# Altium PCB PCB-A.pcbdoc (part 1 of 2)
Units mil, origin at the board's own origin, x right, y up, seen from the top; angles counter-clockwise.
Board outline 6045 x 2702.2 mil, 4 copper layers (Top Layer, Inner1, Inner2, Bottom Layer); 82 components, 118 nets, 419 pads, 214 vias.
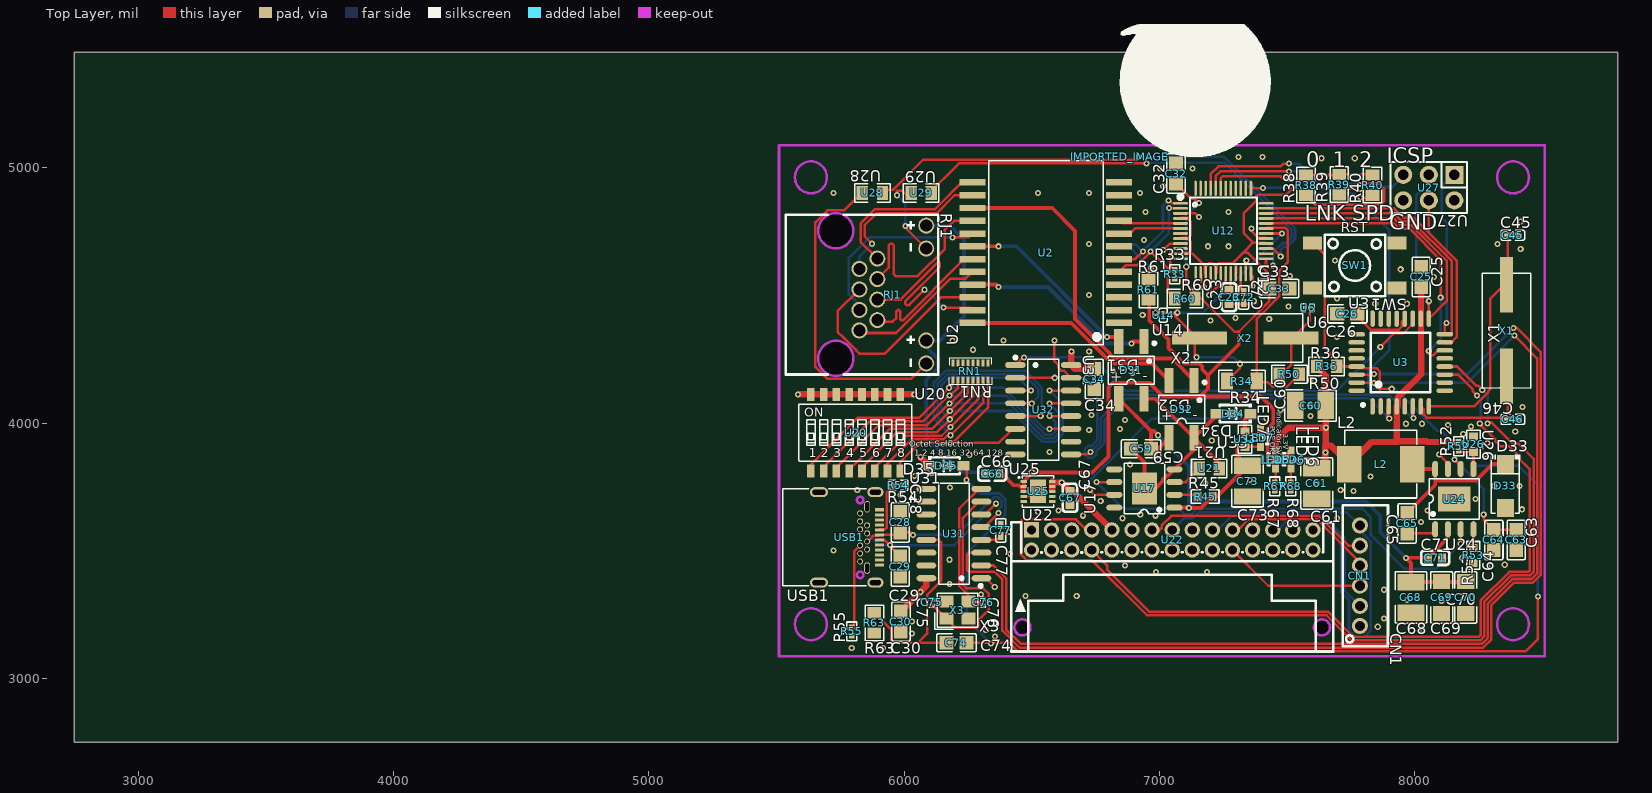
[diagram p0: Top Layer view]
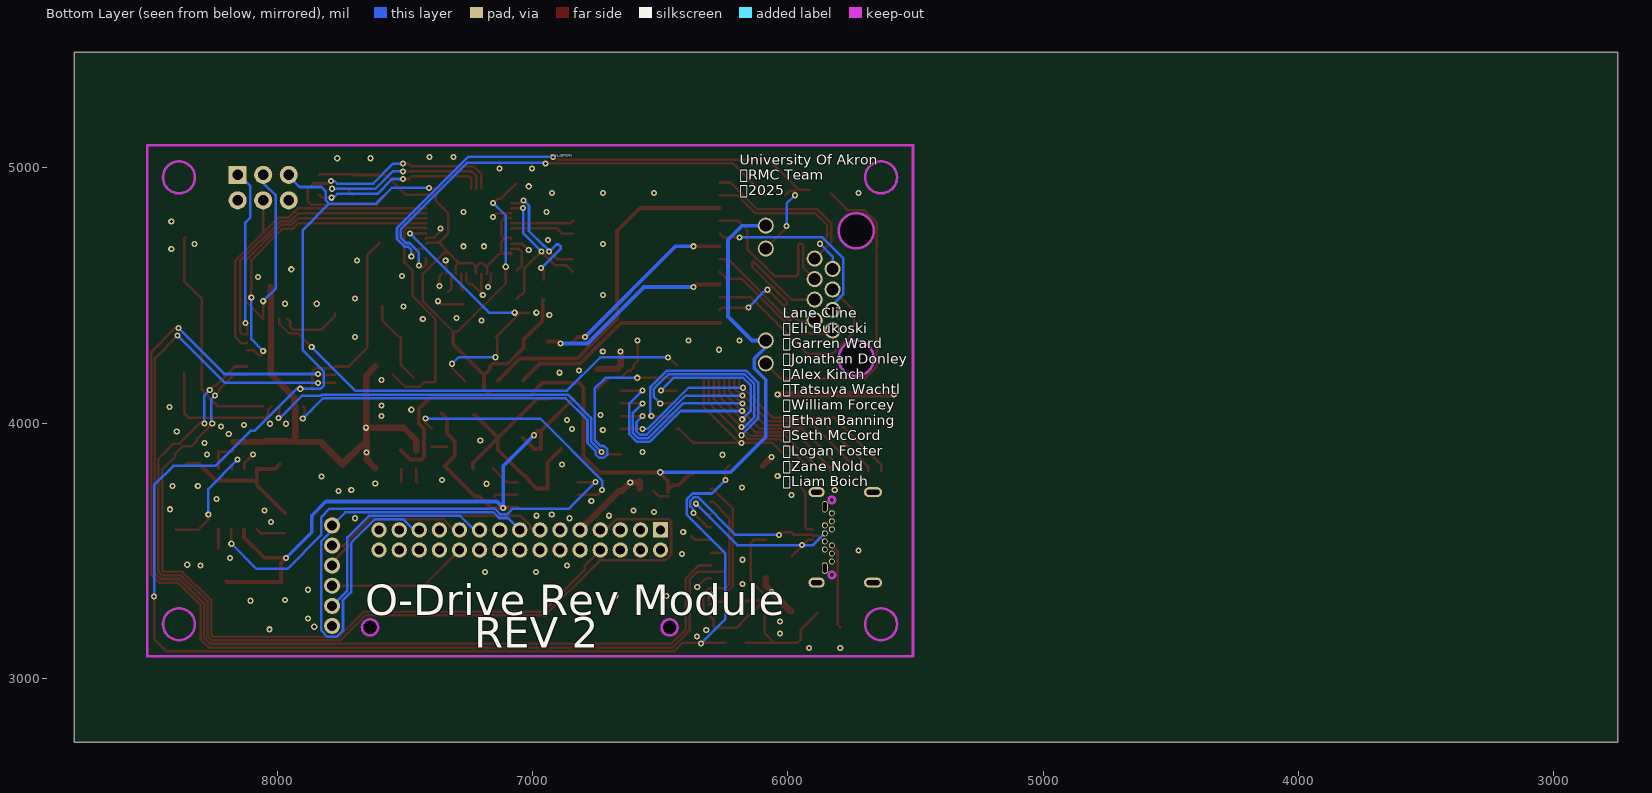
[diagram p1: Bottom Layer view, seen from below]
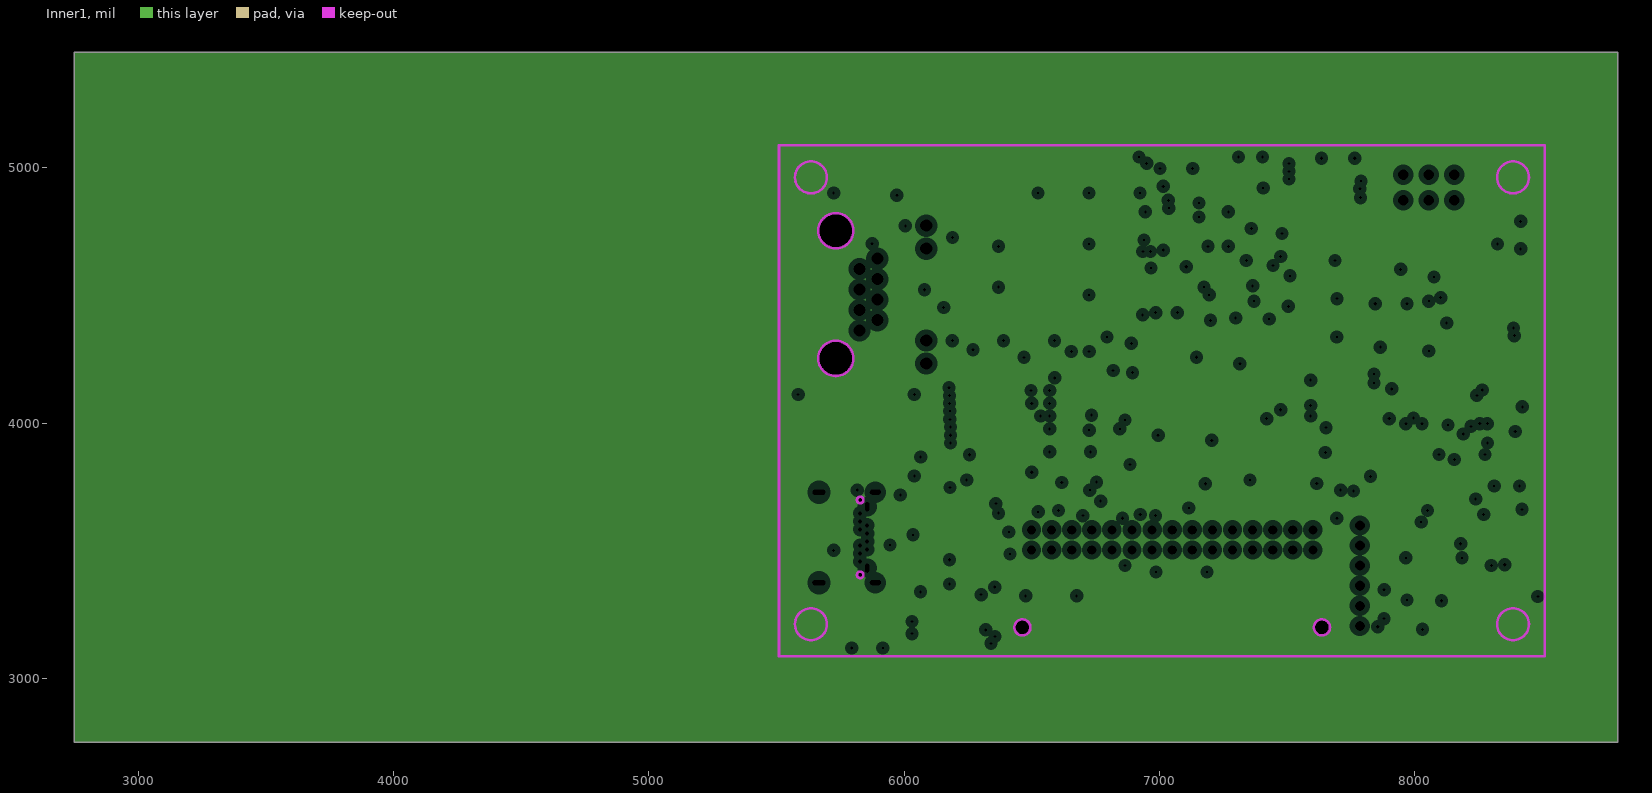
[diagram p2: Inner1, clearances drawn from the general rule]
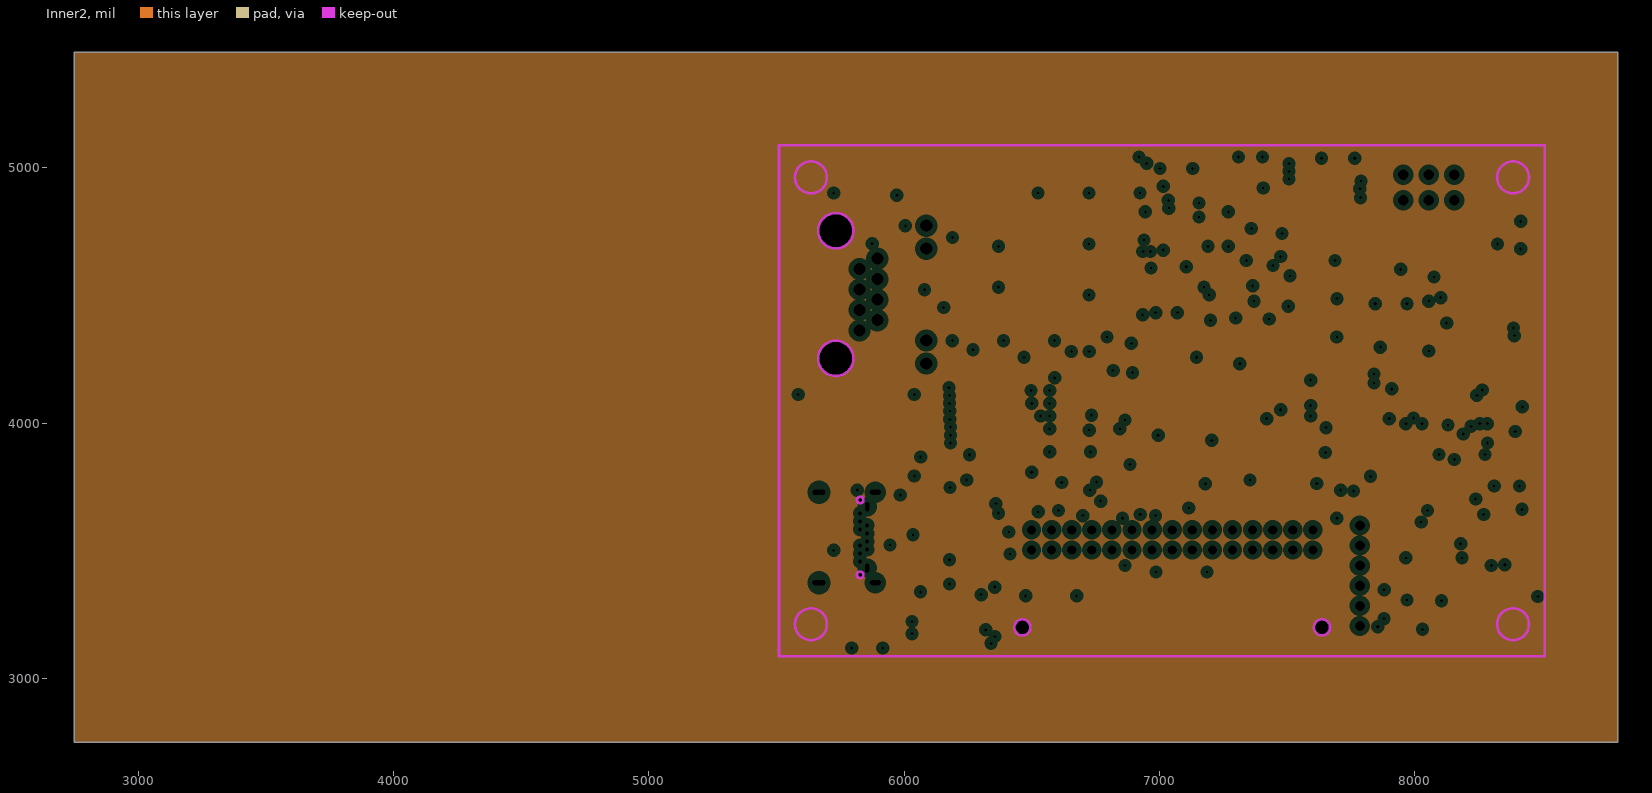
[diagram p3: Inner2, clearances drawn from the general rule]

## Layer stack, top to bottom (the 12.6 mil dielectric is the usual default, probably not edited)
Top Layer: signal copper (thickness not stored)
Dielectric: dielectric 12.6, FR-4, Dk 4.8
Inner1: plane copper (thickness not stored)
Dielectric: dielectric 12.6, FR-4, Dk 4.8
Inner2: plane copper (thickness not stored)
Dielectric: dielectric 12.6, FR-4, Dk 4.8
Bottom Layer: signal copper (thickness not stored)

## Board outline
8795,2750 2750,2750 2750,5452.2 8795,5452.2

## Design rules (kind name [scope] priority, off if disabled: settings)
BoardOutlineClearance copperThickness1oz [All] p0: genericclearance=10 ignorepadtopadclearanceinfootprint=FALSE except(0: Arc-SplitContinuation Track-SplitContinuation SMDPad-SplitContinuation THPad-SplitContinuation Via-SplitContinuation Fill-SplitContinuation Poly-SplitContinuation Region-SplitContinuation Text-SplitContinuation; 6: Track-CutoutEdge SMDPad-CutoutEdge THPad-CutoutEdge Via-CutoutEdge Region-CutoutEdge; 11.8: Track-OutlineEdge SMDPad-OutlineEdge THPad-OutlineEdge Via-OutlineEdge Fill-OutlineEdge Region-OutlineEdge Poly-OutlineEdge Text-OutlineEdge Fill-CutoutEdge)
BoardOutlineClearance copperThickness2oz [All] p0: genericclearance=10 ignorepadtopadclearanceinfootprint=FALSE except(0: Arc-SplitContinuation Track-SplitContinuation SMDPad-SplitContinuation THPad-SplitContinuation Via-SplitContinuation Fill-SplitContinuation Poly-SplitContinuation Region-SplitContinuation Text-SplitContinuation; 6: Track-CutoutEdge SMDPad-CutoutEdge THPad-CutoutEdge Via-CutoutEdge Region-CutoutEdge; 11.8: Track-OutlineEdge SMDPad-OutlineEdge THPad-OutlineEdge Via-OutlineEdge Fill-OutlineEdge Region-OutlineEdge Poly-OutlineEdge Text-OutlineEdge Fill-CutoutEdge)
Clearance copperThickness1oz [(InNet('D2') OR InNet('D3') OR InNet('D4') OR InNet('D5') OR InNet('D6') OR InNet('D7') OR InNet('D8') OR InNet('A0') OR InNet('A1') OR InNet('A2') OR InNet('A3') OR InNet('A4') OR InNet('A5') OR InNet('A6') OR InNet('A7') OR InNet('D9') OR InNet('W5500INT') OR InNet('+5V') OR InNet('ETH1A') OR InNet('ETH1B') OR InNet('ETH2A') OR InNet('ETH2B') OR InNet('ETH3A') OR InNet('ETH3B') OR InNet('ETH4A') OR InNet('ETH4B') OR InNet('+33V') OR InNet('RST') OR InNet('DP1') OR InNet('DN1') OR InNet('MISO') OR InNet('SCLK') OR InNet('MOSI') OR InNet('IP5') OR InNet('IP6') OR InNet('IP3') OR InNet('IP4') OR InNet('IP0') OR InNet('IP2') OR InNet('IP1') OR InNet('IP7') OR InNet('D1') OR InNet('D0') OR InNet('W5500CS') OR InNet('OCTR') OR InNet('OCTCLK') OR InNet('AGND') OR InNet('LINKLED') OR InNet('RJ4B') OR InNet('RJ4A') OR InNet('RJ3B') OR InNet('RJ1B') OR InNet('RJ1A') OR InNet('RJ3A') OR InNet('RJ2B') OR InNet('RJ2A') OR InNet('HALL_C') OR InNet('HALL_B') OR InNet('HALL_A') OR InNet('THERMISTOR+') OR InNet('CAN_H') OR InNet('CAN_L') OR InNet('ODRV12IN') OR InNet('ODRV33V') OR InNet('DIR') OR InNet('STEP') OR InNet('THERMISTOR-') OR InNet('ENCO_A') OR InNet('ENCO_B') OR InNet('ENCO_Z') OR InNet('RS_485A') OR InNet('RS_485B') OR InNet('ODRVSPI_MOSI') OR InNet('ODRVSPI_MISO') OR InNet('ODRVSPI_SCK') OR InNet('ODRVSPI_CS') OR InNet('XTAL2') OR InNet('XTAL1') OR InNet('CAN_H2') OR InNet('CAN_L2') OR InNet('$8N818') OR InNet('$8N822') OR InNet('$9N2639') OR InNet('$8N817') OR InNet('$8N825') OR InNet('$8N824') OR InNet('$8N1422') OR InNet('$8N1426') OR InNet('$8N1431') OR InNet('$8N831') OR InNet('$9N2658') OR InNet('POE+') OR InNet('POE-') OR InNet('CDB') OR InNet('ODRV5V') OR InNet('$6N40771') OR InNet('$6N40777') OR InNet('$6N40772') OR InNet('$6N40746') OR InNet('$6N40745') OR InNet('$6N40747') OR InNet('$6N40762') OR InNet('$6N40753') OR InNet('$6N40759') OR InNet('$6N40758') OR InNet('$6N40773') OR InNet('$6N40770') OR InNet('$6N40752') OR InNet('$9N10840') OR InNet('ACTLED') OR InNet('$6N43649') OR InNet('$9N12898') OR InNet('$9N13149') OR InNet('$9N13153') OR InNet('$9N4435') OR InNet('$6N49390') OR InNet('$6N49466') OR InNet('$6N43810'))] p1: gap=7 ignorepadtopadclearanceinfootprint=FALSE except(4: Track-Track; 6: Track-SMDPad SMDPad-SMDPad Track-THPad SMDPad-THPad THPad-THPad Track-Via SMDPad-Via THPad-Via Via-Via SMDPad-Fill THPad-Fill Via-Fill Fill-Fill Track-Region SMDPad-Region THPad-Region Via-Region Region-Region Track-Poly SMDPad-Poly THPad-Poly Via-Poly Fill-Poly Region-Poly Poly-Poly Track-Text SMDPad-Text THPad-Text Via-Text Fill-Text Region-Text Poly-Text Text-Text; 6.9: Track-Hole SMDPad-Hole THPad-Hole Via-Hole Fill-Hole Region-Hole Poly-Hole Text-Hole Sheet-Hole; 11.8: Track-Fill Fill-Region Track-Sheet SMDPad-Sheet THPad-Sheet Via-Sheet Fill-Sheet Region-Sheet Poly-Sheet Text-Sheet)
Clearance copperThickness2oz [All] p1: gap=7 ignorepadtopadclearanceinfootprint=FALSE except(6: Track-SMDPad SMDPad-SMDPad Track-THPad SMDPad-THPad THPad-THPad Track-Via SMDPad-Via THPad-Via Via-Via SMDPad-Fill THPad-Fill Via-Fill Fill-Fill Track-Region SMDPad-Region THPad-Region Via-Region Region-Region Track-Poly SMDPad-Poly THPad-Poly Via-Poly Fill-Poly Region-Poly Poly-Poly Track-Text SMDPad-Text THPad-Text Via-Text Fill-Text Region-Text Poly-Text Text-Text; 6.9: Track-Hole SMDPad-Hole THPad-Hole Via-Hole Fill-Hole Region-Hole Poly-Hole Text-Hole Sheet-Hole; 8: Track-Track; 11.8: Track-Fill Fill-Region Track-Sheet SMDPad-Sheet THPad-Sheet Via-Sheet Fill-Sheet Region-Sheet Poly-Sheet Text-Sheet)
DiffPairsRouting differentialPair [All] p1: maxuncoupledlength=10 minlimit=6 maxlimit=6 mostfreqgap=6 toplayer_minwidth=5 toplayer_prefwidth=10 toplayer_maxwidth=100 bottomlayer_minwidth=5 bottomlayer_prefwidth=10 bottomlayer_maxwidth=100
DiffPairsRouting differentialPair1 [All] p1: maxuncoupledlength=10 minlimit=6 maxlimit=6 mostfreqgap=6 toplayer_minwidth=5 toplayer_prefwidth=10 toplayer_maxwidth=100 bottomlayer_minwidth=5 bottomlayer_prefwidth=10 bottomlayer_maxwidth=100
PasteMaskExpansion pasteMaskExpansion [All] p1: expansion=0
PlaneConnect innerPlane [All] p1: planeconnectstyle=Relief reliefexpansion=20 reliefentries=4 reliefconductorwidth=10 reliefairgap=10
PolygonConnect copperRegion [All] p1: connectstyle=Relief reliefentries=4 reliefconductorwidth=10 polygonreliefangle="90 Angle" airgapwidth=10
RoutingVias viaSize [All] p1: viastyle="Through Hole" holewidth=12 minholewidth=11.8 maxholewidth=248 width=24 minwidth=19.7 maxwidth=393.7
SolderMaskExpansion solderMaskExpansion [All] p1: useseparateexpansions=TRUE expansion=2 expansionbottom=2
Width copperThickness1oz [All] p1: maxlimit=100 minlimit=5 preferedwidth=10
Width copperThickness2oz [All] p1: maxlimit=100 minlimit=8 preferedwidth=10
Width powa [All] p1: maxlimit=50 minlimit=10 preferedwidth=25
Width 3v [All] p1: maxlimit=100 minlimit=10 preferedwidth=15

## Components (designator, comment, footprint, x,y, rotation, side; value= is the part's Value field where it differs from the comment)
C23 "CL10A475KQ8NNNC" C0603 7272.81,4493.05 r90 top
C25 "0805B104K500NT" C0805 8025,4572.2 r90 top
C26 "0805B104K500NT" C0805 7735.69,4427.45 r0 top
C28 "CL21C470JBANNNC" C0805 5985.4,3611.27 r270 top
C29 "CL21C470JBANNNC" C0805 5985.4,3438.01 r90 top
C30 "0805B104K500NT" C0805 5987.65,3222.62 r270 top
C32 "0805B104K500NT" C0805 7065,4977.2 r90 top
C33 "0805B104K500NT" C0805 7469.25,4526.84 r0 top
C34 "0805B104K500NT" C0805 6745,4172.2 r90 top
C45 "CC0402JRNPO9BN120" C0402 8383.97,4735.62 r0 top
C46 "CC0402JRNPO9BN120" C0402 8383.97,4014.2 r180 top
C59 "0805B104K500NT" C0805 6928.25,3898.93 r180 top
C60 "CS3225X7R476K160NRL" C1210 7592.35,4068.58 r0 top
C61 "CS3225X7R476K160NRL" C1210 7616.27,3763.58 r90 top
C63 "0805F403M500NT" C0805 8397.35,3542.2 r90 top
C64 "0805F403M500NT" C0805 8310,3542.2 r90 top
C65 "0805B104K500NT" C0805 7970,3607.2 r270 top
C66 "CL10A225KO8NNNC" C0603 6345,3802.2 r0 top
C67 "CL10A225KO8NNNC" C0603 6650,3707.2 r90 top
C68 "FS32X106K101EGG" C1210 7985,3317.2 r90 top
C69 "CC1206KKX7R0BB225" C1206 8105,3317.2 r90 top
C70 "CC1206KKX7R0BB225" C1206 8200,3317.2 r90 top
C71 "CC0603KRX7R0BB104" C0603 8080,3472.2 r180 top
C72 "CC0402KRX7R9BB103" C0402 7330,4492.2 r90 top
C73 "FS32X106K101EGG" C1210 7345,3772.2 r90 top
C74 "0805B104K500NT" C0805 6205.1,3139.54 r180 top
C75 "GRM0225C1E220JA02L" C01005 6107.61,3297.22 r270 top
C76 "GRM0225C1E220JA02L" C01005 6310,3297.22 r270 top
C77 "CC0402JRNPO9BN120" C0402 6379.22,3579.54 r270 top
CN1 "B6B-PH-K-S(LF)(SN)_C131342" CONN-TH_B6B-PH-K-S 7785,3402.2 r270 top
D31 "MB110S_C382811" MBS_L4.7-W4.0-P2.50-LS7.0-BL 6890,4207.2 r180 top
D32 "MB110S_C382811" MBS_L4.7-W4.0-P2.50-LS7.0-BL 7086.86,4054.47 r180 top
D33 "SS36_C727061" SMA_L4.4-W2.6-LS5.0-RD 8355,3753.58 r270 top
D34 "LMSZ5264BT1G" SOD-123_L2.7-W1.6-LS3.7-RD-1 7290,4037.2 r180 top
D35 "LMSZ5264BT1G" SOD-123_L2.7-W1.6-LS3.7-RD-1 6165,3832.2 r0 top
IMPORTED_IMAGE "IMPORTED_IMAGE" IMPORTED_IMAGE 6845,5042.2 r0 top
L2 "FXL0630-8R2-M" IND-SMD_L7.0-W6.6_FXL0630 7867.3,3839.33 r0 top
LED5 "TJ-S1706SW6TGLC7K-A5" LED-SMD_L1.7-W0.6-RD_GREEN 7455,3857.2 r90 top
LED6 "TJ-S1706SW6TGLC7K-A5" LED-SMD_L1.7-W0.6-RD_GREEN 7515,3857.2 r90 top
LED7 "TJ-S1706SW6TGLC7K-A5" LED-SMD_L1.7-W0.6-RD_GREEN 7395,3942.2 r270 top
R33 "0402WGF1242TCE" R0402 7060,4582.2 r90 top
R34 "1206W4F1004T5E" R1206 7323.04,4164.46 r0 top
R36 "0805W8F1002T5E" R0805 7655,4222.2 r0 top
R38 "0805W8F0000T5E_C17477" R0805 7574.25,4932.09 r90 top
R39 "0805W8F0000T5E_C17477" R0805 7704.25,4934.19 r90 top
R40 "0805W8F0000T5E_C17477" R0805 7835,4932.2 r90 top
R45 "0603WAF2492T5E" R0603 7178.87,3712.2 r0 top
R50 "RC0805JR-070RL" R0805 7508.76,4191.15 r0 top
R52 "RC0402FR-07100KL" R0402 8172.16,3908.58 r90 top
R53 "0603WAF4992T5E" R0603 8229.36,3481.61 r90 top
R54 "0402WGF5101TCE" R0402 5977,3757.2 r0 top
R55 "0402WGF5101TCE" R0402 5795,3183.67 r270 top
R60 "0805W8F499JT5E" R0805 7100,4487.2 r0 top
R61 "0805W8F499JT5E" R0805 6956.59,4521.76 r270 top
R63 "0805W8F1001T5E" R0805 5883.35,3217.16 r270 top
R67 "RC0402FR-071K78L" R0402 7451.14,3751.59 r90 top
R68 "RC0402FR-07845RL" R0402 7515,3751.59 r90 top
RJ1 "HC-RJ45-5JA-1-5" RJ45-TH_HC-RJ45-5JA-1-5 5955.86,4503.19 r270 top
RN1 "EXB2HV103JV" RES-ARRAY-SMD_16P-L3.8-W1.6-P0.50-BL 6260,4202.2 r180 top
SW1 "PTS645SK50SMTR92LFS" KEY-SMD_4P-L6.0-W6.0-P4.50-LS9.0 7765,4617.2 r180 top
U2 "G24102CE-Z" SMD-24_L18.2-W12.2-P1.27_G24102CE-Z 6555,4667.2 r90 top
U3 "ATMEGA328PB-AU" TQFP-32_L7.0-W7.0-P0.80-LS9.0-BL 7945,4237.2 r0 top
U6 "GJM0335C1E180GB01D" C0201 7580,4452.2 r0 top
U12 "W5500" LQFP-48_L7.0-W7.0-P0.50-LS9.0-BL 7250,4752.2 r270 top
U14 "GJM0335C1E180GB01D" C0201 7015,4422.2 r90 top
U17 "TPS2378DDAR" SO-8_L4.9-W3.9-P1.27-LS6.0-BL-EP 6941.2,3743.93 r90 top
U20 "DV7SA-08F-01" SW-SMD_DV7SA-08F-01 5810,3962.2 r0 top
U21 "CR0805F863R4G" R0805 7195,3822.2 r180 top
U22 "S30B-PUDSS-1(LF)(SN)" CONN-TH_S30B-PUDSS-1 7050,3542.2 r0 top
U24 "LMR16030SDDAR" SO-8_L4.9-W3.9-P1.27-LS6.0-BL-EP 8155,3702.2 r0 top
U25 "NCP3335AMN330R2G" DFN-10_L3.0-W3.0-P0.50-BL-EP-1 6525,3732.2 r270 top
U26 "FRC0603F1782TS" R0603 8230,3917.2 r270 top
U27 "ZX-PZ2.54-2-3PZZ" HDR-TH_6P-P2.54-V-M-R2-C3-S2.54-1 8055,4922.2 r180 top
U28 "CR0805F863R4G" R0805 5876.13,4901.35 r180 top
U29 "CR0805F863R4G" R0805 6066.77,4901.35 r180 top
U31 "CH340G" SOIC-16_L9.9-W3.9-P1.27-LS6.0-BL 6195,3567.2 r90 top
U32 "SN74HC165DTR(XBLW)" SOP-16_L9.9-W3.9-P1.27-LS6.0-BL 6545,4052.2 r270 top
U33 "FRC0603F2672TS" R0603 7335,3936.56 r270 top
USB1 "HC-TYPE-C-24P-DS10.0-CH2.75S-5A-04" USB-TYPE-C-SMD_HC-TYPE-C-24P-DS10.0-CH2.75S-5A-04 5785,3552.2 r270 top
X1 "X49SM16MSD2SC" HC-49S_L11.4-W4.8 8360,4362.2 r90 top
X2 "X49SM25MSD2SC" HC-49S_L11.4-W4.8 7336.19,4332.31 r0 top
X3 "X322512MOB4SI" CRYSTAL-SMD_4P-L3.2-W2.5-BL 6208.84,3267.19 r0 top

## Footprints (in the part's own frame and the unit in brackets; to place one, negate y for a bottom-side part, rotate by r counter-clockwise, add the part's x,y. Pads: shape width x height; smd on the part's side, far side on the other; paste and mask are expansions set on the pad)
C0201 [mil]
  rect 14.51x12.76 smd: 1(-10.8,0) 2(10.8,0)
  silkscreen extent -27,-15 27,15
C0402 [mm]
  rect 0.79x0.54 smd: 1(-0.545,0) 2(0.545,0)
  silkscreen extent -1.17,-0.5 1.17,0.5
C0603 [mm]
  rect 0.8x0.9 smd: 1(-0.7,0) 2(0.7,0)
  silkscreen extent -1.41,-0.71 1.39,0.72
C0805 [mm]
  rect 1.41x1.35 smd: 1(-1,0) 2(1,0)
  silkscreen extent -1.96,-0.9 1.96,0.9
C01005 [mm]
  rect 0.21x0.22 smd: 1(-0.195,0) 2(0.195,0)
  silkscreen extent -0.46,-0.27 0.46,0.27
C1206 [mm]
  rect 1.485x1.728 smd: 1(-1.593,0) 2(1.593,0)
  silkscreen extent -2.56,-1.09 2.56,1.09
C1210 [mm]
  rect 1.635x2.7 smd: 1(-1.517,0) 2(1.517,0)
  silkscreen extent -2.56,-1.58 2.56,1.58
CONN-TH_B6B-PH-K-S [mm]
  round 1.6 hole 1: 1(5,0) 2(3,0) 3(1,0) 4(-1,0) 5(-3,0) 6(-5,0)
  silkscreen extent -7,-1.7 7,2.8
CONN-TH_S30B-PUDSS-1 [mil]
  rect 60x60 hole 36: 1(-551.18,39.37)
  round 60 hole 36: 2(-551.18,-39.37) 3(-472.44,39.37) 4(-472.44,-39.37) 5(-393.7,39.37) 6(-393.7,-39.37) 7(-314.96,39.37) 8(-314.96,-39.37) 9(-236.22,39.37) 10(-236.22,-39.37) 11(-157.48,39.37) 12(-157.48,-39.37) 13(-78.74,39.37) 14(-78.74,-39.37) 15(0,39.37) 16(0,-39.37) 17(78.74,39.37) 18(78.74,-39.37) 19(157.48,39.37) 20(157.48,-39.37) 21(236.22,39.37) 22(236.22,-39.37) 23(314.96,39.37) 24(314.96,-39.37) 25(393.7,39.37) 26(393.7,-39.37) 27(472.44,39.37) 28(472.44,-39.37) 29(551.18,39.37) 30(551.18,-39.37)
  Board Outline Layer circle w0.2: c-586.61,-342.52 r31.5
  Board Outline Layer circle w0.2: c586.61,-342.52 r31.5
  Board Outline Layer circle w10: c-586.61,-342.52 r31.5
  Board Outline Layer circle w10: c586.61,-342.52 r31.5
  Multi-Layer board cut-out: -555.12,-342.52 -559.34,-326.77 -570.86,-315.24 -586.61,-311.02 -602.36,-315.24 -613.89,-326.77 -618.11,-342.51 -618.11,-342.51 -614.99,-356.18 -606.25,-367.14 -593.62,-373.22 -579.61,-373.22 -566.98,-367.14 -558.24,-356.18 -555.12,-342.52
  Multi-Layer board cut-out: 618.11,-342.52 613.79,-326.9 602.28,-315.5 586.62,-311.33 570.96,-315.5 559.44,-326.9 555.12,-342.51 555.12,-342.51 559.44,-358.13 570.95,-369.54 586.61,-373.71 602.27,-369.54 613.79,-358.14 618.11,-342.52
  silkscreen extent -630,-437 630,69
CRYSTAL-SMD_4P-L3.2-W2.5-BL [mm]
  rect 1.4x1.2 smd: 1(-1.1,-0.85) 2(1.1,-0.85) 3(1.1,0.85) 4(-1.1,0.85)
  silkscreen extent -2.26,-1.91 2.03,1.68
DFN-10_L3.0-W3.0-P0.50-BL-EP-1 [mm]
  rect 0.29x0.65 smd: 1(-1,-1.411) 2(-0.5,-1.411) 3(0,-1.411) 4(0.5,-1.411) 5(1,-1.411) 6(1,1.411) 7(0.5,1.411) 8(0,1.411) 9(-0.5,1.411) 10(-1,1.411)
  rect 2.35x1.58 smd: 11(0,0)
  silkscreen extent -1.58,-1.98 1.58,1.58
HC-49S_L11.4-W4.8 [mm]
  rect 5.5x1.3 smd: 1(-4.553,0) 2(4.553,0)
  silkscreen extent -5.71,-2.41 5.71,2.41
HDR-TH_6P-P2.54-V-M-R2-C3-S2.54-1 [mm]
  rect 1.8x1.8 hole 1.05: 1(-2.54,-1.27)
  round 1.8 hole 1.05: 2(-2.54,1.27) 3(0,-1.27) 4(0,1.27) 5(2.54,-1.27) 6(2.54,1.27)
  silkscreen extent -3.81,-2.54 3.81,2.54
IMPORTED_IMAGE [mil]
  silkscreen extent 0,0 591,628
IND-SMD_L7.0-W6.6_FXL0630 [mm]
  rect 2.424x3.62 smd: 1(3.128,0) 2(-3.128,0)
  silkscreen extent -3.58,-3.38 3.58,3.38
KEY-SMD_4P-L6.0-W6.0-P4.50-LS9.0 [mm]
  rect 1.9x1.3 smd: 1(-4.2,2.25) 2(4.2,2.25) 3(-4.2,-2.25) 4(4.2,-2.25)
  silkscreen extent -3.05,-3.05 2.98,3.05
LED-SMD_L1.7-W0.6-RD_GREEN [mm]
  rect 0.8x0.7 smd: 1(-0.9,0) 2(0.9,0)
  silkscreen extent -0.59,-0.32 0.61,0.8
LQFP-48_L7.0-W7.0-P0.50-LS9.0-BL [mm]
  oval 0.27x1.5 smd: 1(-2.75,-4.25) 2(-2.25,-4.25) 3(-1.75,-4.25) 4(-1.25,-4.25) 5(-0.75,-4.25) 6(-0.25,-4.25) 7(0.25,-4.25) 8(0.75,-4.25) 9(1.25,-4.25) 10(1.75,-4.25) 11(2.25,-4.25) 12(2.75,-4.25) 25(2.75,4.25) 26(2.25,4.25) 27(1.75,4.25) 28(1.25,4.25) 29(0.75,4.25) 30(0.25,4.25) 31(-0.25,4.25) 32(-0.75,4.25) 33(-1.25,4.25) 34(-1.75,4.25) 35(-2.25,4.25) 36(-2.75,4.25)
  oval 1.5x0.27 smd: 13(4.25,-2.75) 14(4.25,-2.25) 15(4.25,-1.75) 16(4.25,-1.25) 17(4.25,-0.75) 18(4.25,-0.25) 19(4.25,0.25) 20(4.25,0.75) 21(4.25,1.25) 22(4.25,1.75) 23(4.25,2.25) 24(4.25,2.75) 37(-4.25,2.75) 38(-4.25,2.25) 39(-4.25,1.75) 40(-4.25,1.25) 41(-4.25,0.75) 42(-4.25,0.25) 43(-4.25,-0.25) 44(-4.25,-0.75) 45(-4.25,-1.25) 46(-4.25,-1.75) 47(-4.25,-2.25) 48(-4.25,-2.75)
  silkscreen extent -3.59,-4.46 3.3,3.34
MBS_L4.7-W4.0-P2.50-LS7.0-BL [mm]
  rect 0.91x2.495 smd: 1(-1.25,-2.848) 2(1.25,-2.848) 3(1.25,2.848) 4(-1.25,2.848)
  silkscreen extent -2.44,-2.82 2.29,1.4
R0402 [mm]
  rect 0.566x0.54 smd: 1(-0.433,0) 2(0.433,0)
  silkscreen extent -0.94,-0.5 0.94,0.5
R0603 [mil]
  rect 31.75x34.02 smd: 1(-29.66,0) 2(29.66,0)
  silkscreen extent -55,-26 55,26
R0805 [mm]
  rect 1.133x1.377 smd: 1(-1,0) 2(1,0)
  silkscreen extent -1.76,-0.92 1.76,0.92
R1206 [mil]
  rect 47.54x66.97 smd: 1(-58.22,0) 2(58.22,0)
  silkscreen extent -91,-42 91,42
RES-ARRAY-SMD_16P-L3.8-W1.6-P0.50-BL [mm]
  rect 0.3x0.7 smd: 1(-1.75,-0.833) 2(-1.25,-0.833) 3(-0.75,-0.833) 4(-0.25,-0.833) 5(0.25,-0.833) 6(0.75,-0.833) 7(1.25,-0.833) 8(1.75,-0.833) 9(1.75,0.833) 10(1.25,0.833) 11(0.75,0.833) 12(0.25,0.833) 13(-0.25,0.833) 14(-0.75,0.833) 15(-1.25,0.833) 16(-1.75,0.833)
  silkscreen extent -2.1,-1.3 2.1,1.3
RJ45-TH_HC-RJ45-5JA-1-5 [mm]
  round 1.6 hole 1.2: 1(3.57,-3.325) 2(2.55,-1.545) 3(1.53,-3.325) 4(0.51,-1.545) 5(-0.51,-3.325) 6(-1.53,-1.545) 7(-2.55,-3.325) 8(-3.57,-1.545) 9(-6.85,3.325) 10(-4.57,3.325) 11(4.57,3.325)
  round 1.6 hole 1.2 copper offset 0,0: 12(6.85,3.325)
  Board Outline Layer circle w0.005: c-6.35,-5.675 r1.75
  Board Outline Layer circle w0.005: c6.35,-5.675 r1.75
  Board Outline Layer circle w0.254: c-6.35,-5.675 r1.75
  Board Outline Layer circle w0.254: c6.35,-5.675 r1.75
  Multi-Layer board cut-out: -6.35,-3.925 -7.219,-4.164 -7.853,-4.804 -8.085,-5.675 -7.853,-6.546 -7.219,-7.186 -6.35,-7.425 -6.35,-7.425 -5.481,-7.185 -4.847,-6.546 -4.615,-5.675 -4.847,-4.804 -5.481,-4.164 -6.35,-3.925
  Multi-Layer board cut-out: 6.35,-3.925 5.481,-4.164 4.847,-4.804 4.615,-5.675 4.847,-6.546 5.481,-7.186 6.35,-7.425 6.35,-7.425 7.219,-7.185 7.853,-6.546 8.085,-5.675 7.853,-4.804 7.219,-4.164 6.35,-3.925
  silkscreen extent -7.95,-10.65 7.95,4.5
SMA_L4.4-W2.6-LS5.0-RD [mm]
  rect 1.8x1.7 smd: 1(-2.193,0) 2(2.193,0)
  silkscreen extent -3.11,-1.48 2.73,1.48
SMD-24_L18.2-W12.2-P1.27_G24102CE-Z [mm]
  rect 0.644x2.6 smd: 1(-6.985,-7.3) 2(-5.715,-7.3) 3(-4.445,-7.3) 4(-3.175,-7.3) 5(-1.905,-7.3) 6(-0.635,-7.3) 7(0.635,-7.3) 8(1.905,-7.3) 9(3.175,-7.3) 10(4.445,-7.3) 11(5.715,-7.3) 12(6.985,-7.3) 13(6.985,7.3) 14(5.715,7.3) 15(4.445,7.3) 16(3.175,7.3) 17(1.905,7.3) 18(0.635,7.3) 19(-0.635,7.3) 20(-1.905,7.3) 21(-3.175,7.3) 22(-4.445,7.3) 23(-5.715,7.3) 24(-6.985,7.3)
  silkscreen extent -9.14,-5.7 9.14,5.7
SO-8_L4.9-W3.9-P1.27-LS6.0-BL-EP [mm]
  oval 0.6x1.6 smd: 1(-1.905,-3) 2(-0.635,-3) 3(0.635,-3) 4(1.905,-3) 5(1.905,3) 6(0.635,3) 7(-0.635,3) 8(-1.905,3)
  rect 3.2x2.5 smd: 9(0,0)
  silkscreen extent -2.5,-2 2.5,2
SOD-123_L2.7-W1.6-LS3.7-RD-1 [mm]
  rect 1.2x0.95 smd: 1(-1.7,0) 2(1.7,0)
  silkscreen extent -1.81,-0.98 1.35,0.98
SOIC-16_L9.9-W3.9-P1.27-LS6.0-BL [mil]
  oval 23.7x77.6 smd: 1(-175,-107.7) 2(-125,-107.7) 3(-75,-107.7) 4(-25,-107.7) 5(25,-107.7) 6(75,-107.7) 7(125,-107.7) 8(175,-107.7) 9(175,107.7) 10(125,107.7) 11(75,107.7) 12(25,107.7) 13(-25,107.7) 14(-75,107.7) 15(-125,107.7) 16(-175,107.7)
  silkscreen extent -211,-111 198,60
SOP-16_L9.9-W3.9-P1.27-LS6.0-BL [mil]
  oval 22.6x80.24 smd: 1(-175,-109.02) 2(-125,-109.02) 3(-75,-109.02) 4(-25,-109.02) 5(25,-109.02) 6(75,-109.02) 7(125,-109.02) 8(175,-109.02) 9(175,109.02) 10(125,109.02) 11(75,109.02) 12(25,109.02) 13(-25,109.02) 14(-75,109.02) 15(-125,109.02) 16(-175,109.02)
  silkscreen extent -210,-115 198,60
SW-SMD_DV7SA-08F-01 [mm]
  rect 0.76x1.27 smd: 1(-4.445,-3.81) 2(-3.175,-3.81) 3(-1.905,-3.81) 4(-0.635,-3.81) 5(0.635,-3.81) 6(1.905,-3.81) 7(3.175,-3.81) 8(4.445,-3.81) 9(4.445,3.81) 10(3.175,3.81) 11(1.905,3.81) 12(0.635,3.81) 13(-0.635,3.81) 14(-1.905,3.81) 15(-3.175,3.81) 16(-4.445,3.81)
  silkscreen extent -5.64,-2.85 5.61,2.85
TQFP-32_L7.0-W7.0-P0.80-LS9.0-BL [mm]
  oval 0.45x1.65 smd: 1(-2.8,-4.369) 2(-2,-4.369) 3(-1.2,-4.369) 4(-0.4,-4.369) 5(0.4,-4.369) 6(1.2,-4.369) 7(2,-4.369) 8(2.8,-4.369) 17(2.8,4.369) 18(2,4.369) 19(1.2,4.369) 20(0.4,4.369) 21(-0.4,4.369) 22(-1.2,4.369) 23(-2,4.369) 24(-2.8,4.369)
  oval 1.65x0.45 smd: 9(4.381,-2.8) 10(4.381,-2) 11(4.381,-1.2) 12(4.381,-0.4) 13(4.381,0.4) 14(4.381,1.2) 15(4.381,2) 16(4.381,2.8) 25(-4.381,2.8) 26(-4.381,2) 27(-4.381,1.2) 28(-4.381,0.4) 29(-4.381,-0.4) 30(-4.381,-1.2) 31(-4.381,-2) 32(-4.381,-2.8)
  silkscreen extent -3.91,-4.36 2.94,2.95
USB-TYPE-C-SMD_HC-TYPE-C-24P-DS10.0-CH2.75S-5A-04 [mm]
  oval 1x1.6 hole 0.5 slot 1.1 at 90 deg: 25(4.5,2.605) 28(-4.5,2.605)
  oval 1x1.8 hole 0.5 slot 1.3 at 90 deg: 26(4.5,-3.005) 27(-4.5,-3.005)
  rect 0.3x0.9 smd: A1(-2.75,3.005) A2(-2.25,3.005) A3(-1.75,3.005) A4(-1.25,3.005) A5(-0.75,3.005) A6(-0.25,3.005) A7(0.25,3.005) A8(0.75,3.005) A9(1.25,3.005) A10(1.75,3.005) A11(2.25,3.005) A12(2.75,3.005)
  oval 1.15x0.6 hole 0.4 slot 0.9 at 0 deg: B1(3.05,1.795)
  round 0.6 hole 0.4: B2(2.4,1.095) B3(1.6,1.095) B4(1.2,1.795) B5(0.8,1.095) B6(0.4,1.795) B7(-0.4,1.795) B9(-1.2,1.795) B10(-1.6,1.095) B11(-2.4,1.095)
  round 0.6 hole 0.4 copper offset 0,0: B8(-0.8,1.095)
  oval 1.15x0.6 hole 0.4 slot 0.9 at 0 deg copper offset 0,0: B12(-3.05,1.795)
  Board Outline Layer circle w0.005: c-3.725,1.095 r0.325
  Board Outline Layer circle w0.005: c3.725,1.095 r0.325
  Board Outline Layer circle w0.254: c-3.725,1.095 r0.325
  Board Outline Layer circle w0.254: c3.725,1.095 r0.325
  Multi-Layer board cut-out: -3.725,1.42 -3.885,1.374 -4.001,1.256 -4.043,1.095 -4.001,0.934 -3.885,0.816 -3.725,0.77 -3.725,0.77 -3.565,0.816 -3.449,0.934 -3.406,1.095 -3.449,1.256 -3.565,1.374 -3.725,1.42
  Multi-Layer board cut-out: 3.725,1.42 3.565,1.374 3.449,1.256 3.406,1.095 3.449,0.934 3.565,0.816 3.725,0.77 3.725,0.77 3.885,0.816 4.001,0.934 4.044,1.095 4.001,1.256 3.885,1.374 3.725,1.42
  silkscreen extent -4.83,-6.6 4.83,1.71

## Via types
v1: diameter 24, hole 12, Top Layer to Bottom Layer, 173 vias
v2: diameter 24.02, hole 12.01, Top Layer to Bottom Layer, 41 vias

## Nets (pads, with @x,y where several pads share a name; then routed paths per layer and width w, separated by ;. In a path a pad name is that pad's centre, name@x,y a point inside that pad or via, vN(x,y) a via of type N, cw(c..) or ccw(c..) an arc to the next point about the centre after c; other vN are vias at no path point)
$6N40745: D31.2 U2.18 | length 727.6
  Top Layer w15: U2.18@6267.6,4692.2 v1(6370,4692.2) ; v1(6795,4337.2) 6822.89,4337.2 D31.2@6840.78,4319.31
  Bottom Layer w15: v1(6370,4692.2) 6440,4692.2 v1(6795,4337.2)
$6N40746: D31.1 U2.21 | length 770.2
  Top Layer w15: U2.21@6267.6,4542.2 6360,4542.2 v1(6370,4532.2) ; v1(6890,4312.2) 6897.11,4319.31 D31.1@6939.22,4319.31
  Bottom Layer w15: v1(6370,4532.2) 6563.94,4532.2 6784.44,4311.7 6805.56,4311.7 6806.06,4312.2 v1(6890,4312.2)
$6N40747: D32.1 U2.15 | length 1352.3
  Top Layer w15: U2.15@6267.6,4842.2 6580,4842.2 6670,4752.2 6670,4407.2 6809.37,4267.84 6809.37,4264.61 6817.27,4256.7 6820.5,4256.7 6825,4252.2 7050.46,4252.2 D32.1@7136.08,4166.58
$6N40752: U17.3 U21.2 | length 118.4
  Top Layer w10: U17.3@7059.31,3768.93 7102.36,3768.93 U21.2@7155.63,3822.2
$6N40753: R45.1 U17.2 | length 93.8
  Top Layer w10: U17.2@7059.31,3718.93 7143.61,3718.93 R45.1@7150.34,3712.2
$6N40758: RJ1.12 U28.2 | length 1271.7
  Top Layer w10: U28.2@5832.32,4900.2 5765.2,4833.08 5699.34,4833.08 5652.55,4786.28 5652.55,4220.11 5699.34,4173.31 6026.57,4173.31 RJ1.12@6086.77,4233.51
$6N40759: RJ1.10 U29.2 | length 319.5
  Top Layer w10: v2(5971.8,4892.2) 5971.8,4909.01 5972.07,4909.28 5993.56,4909.28 U29.2@6010.63,4892.2 ; v2(6005,4772.2) 6005,4764.88 RJ1.10@6086.77,4683.12
  Bottom Layer w10: v2(5971.8,4892.2) 6005,4859.01 v2(6005,4772.2)
$6N40762: D32.2 U2.24 | length 863.5
  Top Layer w15: U2.24@6267.6,4392.2 6654.9,4392.2 6813.9,4233.2 6971.02,4233.2 D32.2@7037.64,4166.58
$6N40770: R53.2 U24.4 | length 73.1
  Top Layer w10: R53.2@8229.36,3511.27 8230,3511.91 U24.4@8230,3584.1
$6N40771: C63.2 C64.2 U24.6 | length 476
  Top Layer w10: v1(8155,3857.2) 8178.87,3833.33 U24.6@8178.87,3819.19 ; v1(8270,3642.2) 8270,3621.57 C64.2@8310,3581.57 8395.22,3581.57 C63.2@8397.35,3583.71
  Bottom Layer w10: v1(8155,3857.2) 8270,3742.2 v1(8270,3642.2)
$6N40772: C65.1 D33.1 L2.1 U24.8 | length 620.6
  Top Layer w15: C65.1@7970,3646.57 8078.51,3755.08 8078.51,3757.01 8080,3758.5 8080,3780.49 ; L2.1@7990.45,3839.33 8009.47,3820.32 U24.8@8080,3820.32 8080,3780.49 ; D33.1@8355,3839.9 8305.06,3839.9 8240.49,3775.32 8085.17,3775.32 8080,3780.49
$6N40773: R52.1 U24.5 U26.2 | length 126.7
  Top Layer w10: R52.1@8172.16,3891.54 8176.15,3887.54 U26.2@8230,3887.54 U24.5@8230,3820.32
$6N40777: C65.2 U24.1 | length 116.7
  Top Layer w10: C65.2@7970,3567.83 8063.74,3567.83 U24.1@8080,3584.1
$6N43649: LED7.1 U17.7 | length 983.5
  Top Layer w10: v1(6727.5,3737.2) 6745.77,3718.93 U17.7@6823.09,3718.93 ; LED7.1@7395,3977.64 7420,4002.64 v1(7420,4017.2)
  Bottom Layer w10: v1(6727.5,3737.2) 6727.5,3774.7 6970,4017.2 v1(7420,4017.2)
$6N43810: LED7.2 U33.2 | length 60.1
  Top Layer w10: U33.2@7335,3906.9 7394.87,3906.9 LED7.2@7395,3906.77
$6N49390: LED5.1 R67.2 | length 54.7
  Top Layer w10: R67.2@7451.14,3768.63 7455,3772.49 LED5.1@7455,3821.76
$6N49466: LED6.1 R68.2 | length 53.1
  Top Layer w10: R68.2@7515,3768.63 LED6.1@7515,3821.76
$8N817: R33.2 U12.10 | length 124.4
  Top Layer w10: R33.2@7060,4599.24 7042.17,4617.08 7042.17,4670.38 7055.1,4683.3 U12.10@7082.68,4683.3
$8N818: C23.2 U12.20 | length 67.1
  Top Layer w10: C23.2@7272.81,4520.61 7279.53,4527.33 U12.20@7279.53,4584.88
$8N822: C72.2 U12.22 | length 75.8
  Top Layer w10: U12.22@7318.9,4584.88 7318.9,4524.76 C72.2@7330,4513.66
$8N824: R34.1 U12.30 U14.2 X2.1 | length 1143
  Top Layer w10: U14.2@7015.8,4432.2 7047.99,4432.2 ; v2(7070,4432.2) 7047.99,4432.2 ; v2(7145.54,4257.71) 7137.93,4265.32 7137.93,4332.14 7142.99,4337.2 7047.99,4432.2 ; R34.1@7264.82,4164.46 7315,4214.64 v2(7315,4232.2) ; U12.30@7417.32,4742.36 7479.84,4742.36 v2(7480,4742.2)
  Bottom Layer w10: v2(7070,4432.2) 7170,4432.2 v2(7480,4742.2) ; v2(7145.54,4257.71) 7289.49,4257.71 v2(7315,4232.2)
$8N825: R34.2 R50.2 U12.31 | length 928.1
  Top Layer w10: U12.31@7417.32,4762.04 7420.47,4765.2 7492.01,4765.2 7502.99,4754.21 7502.99,4630.2 7469.86,4597.07 7469.86,4496.96 7381.26,4408.36 R34.2@7381.26,4164.46 7386.26,4159.46 7424.66,4159.46 7441.92,4142.2 7499.18,4142.2 R50.2@7548.13,4191.15
$8N831: R50.1 U6.2 X2.2 | length 335.5
  Top Layer w10: R50.1@7465.34,4177.2 7517.01,4228.87 7517.01,4337.2 7524.2,4337.2 7589.2,4402.2 U6.2@7589.2,4457.2
$8N1422: R38.1 U12.45 | length 1177.1
  Top Layer w10: U12.45@7200.79,4919.52 7200.79,4975.36 7230.92,5005.49 7475,5005.49 7485.32,5015.81 v2(7507.33,5015.81) ; R38.1@7574.25,4892.72 7612.16,4854.8 7866.44,4854.8 7880,4868.36 7880,4917.2 7858.91,4938.3 7803.34,4938.3 7794.12,4947.52 v2(7789.9,4947.52)
  Bottom Layer w10: v2(7507.33,5015.81) 7546.39,5015.81 7625,4937.2 7765,4937.2 7775.32,4947.52 v2(7789.9,4947.52)
$8N1426: R39.1 U12.44 | length 738.2
  Top Layer w10: U12.44@7220.47,4919.52 7220.47,4967.21 7239.08,4985.81 v2(7507.33,4985.81) ; R39.1@7704.25,4894.82 7726.95,4917.52 v2(7784.9,4917.52)
  Bottom Layer w10: v2(7507.33,4985.81) 7547.81,4985.81 7616.1,4917.52 v2(7784.9,4917.52)
$8N1431: R40.1 U12.43 | length 676.2
  Top Layer w10: U12.43@7240.16,4919.52 7240.16,4959.05 7247.23,4966.12 7475,4966.12 7485.32,4955.81 v2(7507.33,4955.81) ; v2(7787.33,4882.52) 7824.69,4882.52 R40.1@7835,4892.83
  Bottom Layer w10: v2(7507.33,4955.81) 7549.97,4955.81 7607.94,4897.83 7765,4897.83 7780.32,4882.52 v2(7787.33,4882.52)
$9N2639: C26.2 U3.20 | length 247.1
  Top Layer w10: C26.2@7775.06,4427.45 7775.06,4417.22 7826.54,4365.74 7937.47,4365.74 7949.09,4377.36 7949.09,4397.55 U3.20@7960.75,4409.2
$9N2658: R54.1 USB1.A5 | length 210.4
  Top Layer w10: USB1.A5@5903.31,3581.73 5906.08,3584.51 5925.58,3584.51 5932.03,3590.95 5932.03,3729.27 R54.1@5959.96,3757.2
$9N4435: C77.2 U31.4 | length 83.1
  Top Layer w10: U31.4@6302.7,3542.2 6363.35,3542.2 C77.2@6379.22,3558.08
$9N10840: R55.1 USB1.B5 | length 334.2
  Top Layer w10: R55.1@5795,3200.71 5804.31,3210.02 5804.31,3497.69 5818.65,3512.03 5819.41,3512.03 USB1.B5@5828.11,3520.72
$9N12898: C74.2 R63.1 U31.13 | length 845.8
  Top Layer w10: R63.1@5883.35,3256.53 5950.07,3189.8 5950.07,3150.93 5961.47,3139.54 6053.97,3139.54 ; U31.13@6087.3,3542.2 6135,3542.2 6145,3532.2 6145,3382.2 6090,3327.2 6090,3175.57 6053.97,3139.54 ; C74.2@6165.73,3139.54 6053.97,3139.54
$9N13149: C75.2 U31.7 X3.1 | length 842.9
  Top Layer w10: C75.2@6107.61,3289.54 6109.72,3289.54 X3.1@6165.53,3233.72 6200.16,3199.1 6284.27,3199.1 6290.71,3205.54 6290.71,3227.92 6332.07,3269.28 6332.07,3330.13 6310,3352.2 6245,3352.2 6230,3367.2 6230,3628.77 6293.44,3692.2 U31.7@6302.7,3692.2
